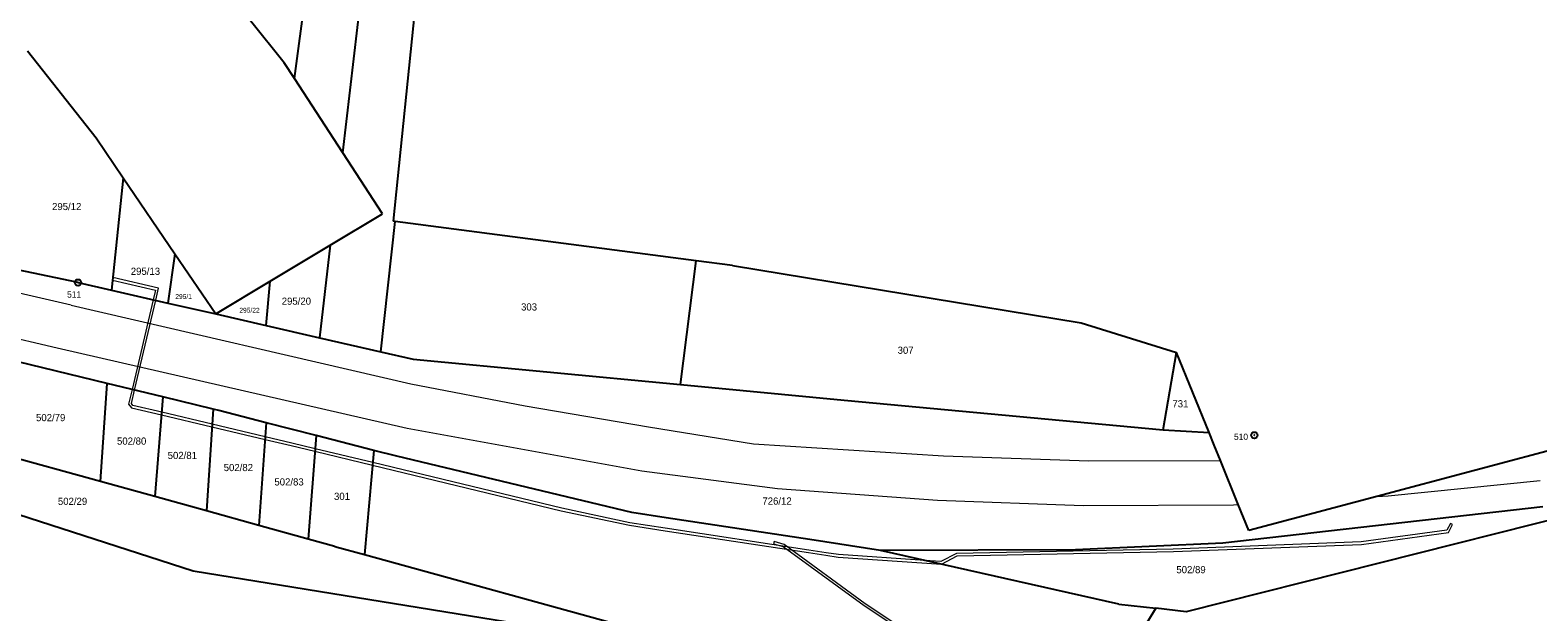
# Model space of a CAD drawing. Extents: x -701211 to -698780, y -1014269 to -1012378.
# Drawn here: x -699972 to -699614.3, y -1012806.8 to -1012668.8 of the extents above; entities that cross this region are included whole.
import ezdxf
from ezdxf.enums import TextEntityAlignment as Align

# ---------------------------------------------------------------- set-up
doc = ezdxf.new("R2010")
doc.units = 0
doc.header["$LTSCALE"] = 0.68
for name, color, linetype, lineweight in [('1', 7, 'Continuous', 25), ('13', 7, 'Continuous', 13), ('4', 7, 'Continuous', 13), ('8', 7, 'Continuous', 25)]:
    doc.layers.add(name, color=color, linetype=linetype, lineweight=lineweight)
doc.layers.add('2', color=7, linetype='Continuous')

msp = doc.modelspace()

# ---------------------------------------------------------------- linework, layer by layer
at = {"layer": '1'}
for p, q in [((-699873.86, -1012596.11), (-699885.89, -1012714.16)), ((-699909.32, -1012680.3), (-699900.81, -1012616.48)), ((-699897.86, -1012697.94), (-699892.07, -1012648.65)), ((-699911.76, -1012676.55), (-699919.73, -1012666.62)), ((-699972.64, -1012673.73), (-699956.4, -1012694.36)), ((-699909.32, -1012680.3), (-699911.76, -1012676.55)), ((-699897.86, -1012697.94), (-699909.32, -1012680.3)), ((-699956.4, -1012694.36), (-699949.93, -1012703.88)), ((-699888.45, -1012712.42), (-699897.86, -1012697.94)), ((-699949.93, -1012703.88), (-699952.74, -1012730.51)), ((-699949.93, -1012703.88), (-699937.69, -1012721.89)), ((-699900.85, -1012719.85), (-699888.45, -1012712.42)), ((-699885.42, -1012714.22), (-699885.89, -1012714.16)), ((-699888.85, -1012745.13), (-699885.42, -1012714.22)), ((-699814.06, -1012723.52), (-699885.42, -1012714.22)), ((-699915.06, -1012728.38), (-699900.85, -1012719.85)), ((-699900.85, -1012719.85), (-699903.39, -1012741.8)), ((-699937.69, -1012721.89), (-699939.34, -1012733.58)), ((-699937.69, -1012721.89), (-699928, -1012736.15)), ((-699817.72, -1012752.91), (-699814.06, -1012723.52)), ((-699805.4, -1012724.65), (-699814.06, -1012723.52)), ((-699805.4, -1012724.65), (-699722.7, -1012738.24)), ((-699960.67, -1012728.7), (-699978.46, -1012724.94)), ((-699928, -1012736.15), (-699915.06, -1012728.38)), ((-699916.06, -1012738.9), (-699915.06, -1012728.38)), ((-699960.67, -1012728.7), (-699952.74, -1012730.51)), ((-699952.74, -1012730.51), (-699939.34, -1012733.58)), ((-699939.34, -1012733.58), (-699928, -1012736.15)), ((-699928, -1012736.15), (-699916.06, -1012738.9)), ((-699916.06, -1012738.9), (-699903.39, -1012741.8)), ((-699722.7, -1012738.24), (-699700.03, -1012745.32)), ((-699903.39, -1012741.8), (-699888.85, -1012745.13)), ((-699888.85, -1012745.13), (-699881.18, -1012746.88)), ((-699703.25, -1012763.63), (-699700.03, -1012745.32)), ((-699692.35, -1012764.28), (-699700.03, -1012745.32)), ((-699953.77, -1012752.64), (-699978.14, -1012746.74)), ((-699881.18, -1012746.88), (-699817.72, -1012752.91)), ((-699940.53, -1012755.84), (-699953.77, -1012752.64)), ((-699817.72, -1012752.91), (-699778.93, -1012756.6)), ((-699940.53, -1012755.84), (-699942.47, -1012779.5)), ((-699928.64, -1012758.72), (-699940.53, -1012755.84)), ((-699778.93, -1012756.6), (-699703.25, -1012763.63)), ((-699928.64, -1012758.72), (-699930.2, -1012782.9)), ((-699927.27, -1012759.05), (-699928.64, -1012758.72)), ((-699916, -1012761.96), (-699927.27, -1012759.05)), ((-699577.27, -1012759.44), (-699652.51, -1012779.48)), ((-699916, -1012761.96), (-699917.76, -1012786.34)), ((-699904.17, -1012765.01), (-699916, -1012761.96)), ((-699703.25, -1012763.63), (-699692.35, -1012764.28)), ((-699904.17, -1012765.01), (-699906.08, -1012789.57)), ((-699890.49, -1012768.53), (-699904.17, -1012765.01)), ((-699691.14, -1012767.26), (-699692.35, -1012764.28)), ((-699689.65, -1012770.94), (-699691.14, -1012767.26)), ((-699955.33, -1012775.94), (-699979.56, -1012769.24)), ((-699890.49, -1012768.53), (-699892.69, -1012793.27)), ((-699885.06, -1012769.93), (-699890.49, -1012768.53)), ((-699829.32, -1012783.31), (-699885.06, -1012769.93)), ((-699685.4, -1012781.41), (-699689.65, -1012770.94)), ((-699582.37, -1012777.73), (-699697.77, -1012806.84)), ((-699933.34, -1012797.21), (-699989.3, -1012779.1)), ((-699930.2, -1012782.9), (-699942.47, -1012779.5)), ((-699613.16, -1012781.91), (-699689.06, -1012790.54)), ((-699682.9, -1012787.58), (-699685.4, -1012781.41)), ((-699652.51, -1012779.48), (-699682.9, -1012787.58)), ((-699917.76, -1012786.34), (-699930.2, -1012782.9)), ((-699821.11, -1012784.57), (-699829.32, -1012783.31)), ((-699787.03, -1012789.72), (-699821.11, -1012784.57)), ((-699906.08, -1012789.57), (-699917.76, -1012786.34)), ((-699899.72, -1012791.33), (-699906.08, -1012789.57)), ((-699899.72, -1012791.33), (-699892.69, -1012793.27)), ((-699770.31, -1012792.26), (-699787.03, -1012789.72)), ((-699724.06, -1012792.14), (-699770.31, -1012792.26)), ((-699713.72, -1012804.99), (-699770.31, -1012792.26)), ((-699689.06, -1012790.54), (-699724.06, -1012792.14)), ((-699892.69, -1012793.27), (-699827.27, -1012811.29)), ((-699850.02, -1012810.7), (-699933.34, -1012797.21)), ((-699704.98, -1012806), (-699722.55, -1012834.53)), ((-699713.72, -1012804.99), (-699704.98, -1012806)), ((-699697.77, -1012806.84), (-699704.98, -1012806))]:
    msp.add_line(p, q, dxfattribs=at)
msp.add_lwpolyline([(-699942.47, -1012779.5), (-699955.33, -1012775.94), (-699953.77, -1012752.64)], dxfattribs=at)
at = {"layer": '13'}
for points in [[(-699952.43, -1012727.54), (-699952.49, -1012728.14), (-699942.3, -1012730.51), (-699942.83, -1012732.78), (-699942.25, -1012732.91), (-699941.58, -1012730.07)], [(-699947.83, -1012754.08), (-699947.25, -1012754.22), (-699942.25, -1012732.91), (-699942.83, -1012732.78)], [(-699890.8, -1012772.04), (-699846.04, -1012782.84), (-699829.87, -1012786.31), (-699821.4, -1012787.6), (-699787.39, -1012792.79), (-699783.26, -1012793.42), (-699780.3, -1012793.87), (-699755.84, -1012795.51), (-699759.76, -1012794.63), (-699780.24, -1012793.27), (-699783.19, -1012792.82), (-699787.32, -1012792.19), (-699821.34, -1012787), (-699829.77, -1012785.71), (-699845.9, -1012782.26), (-699890.75, -1012771.44), (-699904.41, -1012768.14), (-699909.98, -1012766.8), (-699916.24, -1012765.31), (-699928.87, -1012762.32), (-699940.83, -1012759.49), (-699947.65, -1012757.87), (-699948, -1012757.44), (-699947.25, -1012754.22), (-699947.83, -1012754.08), (-699948.66, -1012757.58), (-699947.99, -1012758.41), (-699940.88, -1012760.09), (-699928.91, -1012762.93), (-699916.29, -1012765.92), (-699910.12, -1012767.38), (-699904.46, -1012768.75)], [(-699759.76, -1012794.63), (-699755.84, -1012795.51), (-699752.07, -1012793.57), (-699700.81, -1012792.54), (-699656.21, -1012790.86), (-699635.56, -1012788.04), (-699634.55, -1012786.15), (-699635.08, -1012785.87), (-699635.94, -1012787.48), (-699656.27, -1012790.26), (-699700.83, -1012791.94), (-699752.23, -1012792.97), (-699755.96, -1012794.89)], [(-699726.46, -1012844.89), (-699726.24, -1012851.79), (-699725.54, -1012874.31), (-699725.52, -1012876.19), (-699725.33, -1012898.61), (-699724.83, -1012898.6), (-699725.02, -1012876.54), (-699725.04, -1012874.31), (-699725.74, -1012851.77), (-699725.96, -1012844.89), (-699725.87, -1012837.63), (-699726.46, -1012836.82), (-699753.79, -1012818.3), (-699773.9, -1012804.91), (-699793.15, -1012790.89), (-699795.55, -1012790.19), (-699795.69, -1012790.67), (-699793.37, -1012791.35), (-699774.18, -1012805.31), (-699754.07, -1012818.72), (-699726.82, -1012837.18), (-699726.37, -1012837.79)]]:
    msp.add_lwpolyline(points, close=True, dxfattribs=at)
at = {"layer": '4'}
for p, q in [((-699962.33, -1012734.1), (-700087.55, -1012704.87)), ((-700080.25, -1012717.33), (-699965.64, -1012744.18)), ((-699962.33, -1012734.1), (-699881.68, -1012752.72)), ((-699965.64, -1012744.18), (-699882.62, -1012763.3)), ((-699881.68, -1012752.72), (-699854.59, -1012757.94)), ((-699854.59, -1012757.94), (-699825.37, -1012762.92)), ((-699882.62, -1012763.3), (-699826.93, -1012773.35)), ((-699825.37, -1012762.92), (-699800.45, -1012767)), ((-699800.45, -1012767), (-699755.31, -1012769.8)), ((-699755.31, -1012769.8), (-699720.87, -1012770.98)), ((-699720.87, -1012770.98), (-699689.65, -1012770.94)), ((-699826.93, -1012773.35), (-699794.69, -1012777.57)), ((-699794.69, -1012777.57), (-699756.79, -1012780.36)), ((-699649.87, -1012779.33), (-699613.8, -1012775.68)), ((-699756.79, -1012780.36), (-699722.18, -1012781.63)), ((-699722.18, -1012781.63), (-699686.55, -1012781.48)), ((-699686.55, -1012781.48), (-699685.4, -1012781.41)), ((-699652.51, -1012779.48), (-699649.87, -1012779.33))]:
    msp.add_line(p, q, dxfattribs=at)
at = {"layer": '8'}
for centre, radius in [((-699960.67, -1012728.6998), 0.75), ((-699960.67, -1012728.6998), 0.03), ((-699681.59, -1012764.9298), 0.75), ((-699681.59, -1012764.9298), 0.03)]:
    msp.add_circle(centre, radius, dxfattribs=at)

# ---------------------------------------------------------------- texts
at = {"layer": '2'}
for s, height, p in [('295/12', 1.7, (-699963.36, -1012711.515)), ('295/13', 1.7, (-699944.68, -1012726.885)), ('295/1', 1.14, (-699935.619, -1012732.595)), ('295/22', 1.14, (-699919.989, -1012735.845)), ('295/20', 1.7, (-699908.87, -1012733.975)), ('303', 1.7, (-699853.669, -1012735.345)), ('307', 1.7, (-699764.329, -1012745.615)), ('502/79', 1.7, (-699967.16, -1012761.605)), ('502/80', 1.7, (-699947.95, -1012767.175)), ('502/81', 1.7, (-699935.93, -1012770.585)), ('502/82', 1.7, (-699922.64, -1012773.455)), ('502/83', 1.7, (-699910.61, -1012776.865)), ('301', 1.7, (-699898.049, -1012780.285)), ('726/12', 1.7, (-699794.84, -1012781.405)), ('502/89', 1.7, (-699696.62, -1012797.685))]:
    msp.add_text(s, height=height, dxfattribs=at).set_placement(p, align=Align.CENTER)
for s, p in [('731', (-699701.03, -1012758.325)), ('502/29', (-699965.45, -1012781.475))]:
    msp.add_text(s, height=1.7, dxfattribs=at).set_placement(p)
at = {"layer": '8'}
for s, p in [('511', (-699959.916, -1012732.284)), ('510', (-699683.089, -1012766.047))]:
    msp.add_text(s, height=1.5, dxfattribs=at).set_placement(p, align=Align.RIGHT)

doc.saveas('drawing.dxf')
